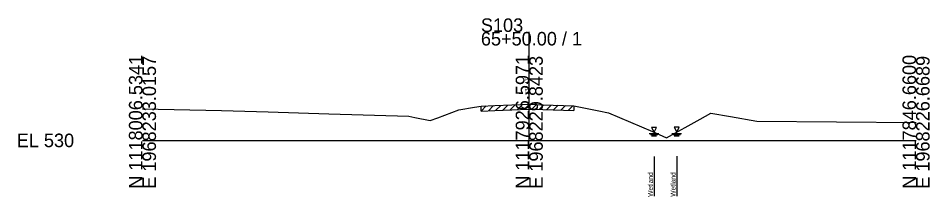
# Model space of a CAD drawing. Extents: x -26 to 163, y -10 to 45020.
# Drawn here: x -25.7 to 162.8, y 24488.3 to 24525.3 of the extents above; entities that cross this region are included whole.
import ezdxf

# ---------------------------------------------------------------- set-up
doc = ezdxf.new("R2010")
doc.units = 0
for name, color, linetype in [('RD_GPK_XS_Cell', 7, 'Continuous'), ('RD_XS_ExGround', 7, 'Continuous'), ('RD_XS_ExPaveRet', 7, 'Continuous'), ('RD_XS_EXWetland', 7, 'Continuous'), ('RD_XS_TX_Elev_EX', 7, 'Continuous')]:
    doc.layers.add(name, color=color, linetype=linetype)

msp = doc.modelspace()

# ---------------------------------------------------------------- linework, layer by layer
at = {"layer": 'RD_GPK_XS_Cell'}
for p, q in [((80, 24500), (80, 24522.43)), ((0, 24500), (80, 24500)), ((80, 24500), (160, 24500))]:
    msp.add_line(p, q, dxfattribs=at)
at = {"layer": 'RD_XS_ExGround'}
for p, q in [((72.86, 24507.2), (79.89, 24507.48)), ((79.89, 24507.48), (82.8, 24507.37)), ((82.8, 24507.37), (89.2, 24507.15)), ((0, 24506.55), (16.38, 24506.19)), ((16.38, 24506.19), (26.01, 24505.93)), ((26.01, 24505.93), (38.54, 24505.52)), ((38.54, 24505.52), (55.09, 24504.98)), ((61.07, 24504.69), (65.47, 24506.33)), ((65.47, 24506.33), (68.7, 24506.86)), ((68.7, 24506.86), (70.04, 24507.08)), ((70.04, 24507.08), (72.86, 24507.2)), ((89.2, 24507.15), (94.37, 24506.12)), ((94.37, 24506.12), (96.38, 24505.69)), ((96.38, 24505.69), (105.48, 24501.84)), ((115.34, 24504.4), (117.53, 24505.64)), ((117.53, 24505.64), (121.62, 24504.94)), ((55.09, 24504.98), (56.34, 24504.75)), ((56.34, 24504.75), (59.53, 24504.1)), ((59.53, 24504.1), (61.07, 24504.69)), ((108.41, 24500.55), (115.34, 24504.4)), ((121.62, 24504.94), (127.08, 24504.01)), ((127.08, 24504.01), (160, 24503.68)), ((105.48, 24501.84), (108.41, 24500.55))]:
    msp.add_line(p, q, dxfattribs=at)
at = {"layer": 'RD_XS_ExPaveRet'}
for p, q in [((76.04, 24506.32), (77.09, 24507.37)), ((77.54, 24506.38), (78.59, 24507.42)), ((79.04, 24506.44), (80.07, 24507.47)), ((80.54, 24506.45), (81.51, 24507.42)), ((82.04, 24506.4), (83.01, 24507.36)), ((70.04, 24506.08), (71.09, 24507.12)), ((70.04, 24506.08), (70.04, 24507.08)), ((70.04, 24506.08), (72.86, 24506.2)), ((71.54, 24506.14), (72.59, 24507.19)), ((72.86, 24506.2), (79.89, 24506.48)), ((73.04, 24506.21), (74.09, 24507.25)), ((74.54, 24506.27), (75.59, 24507.31)), ((79.89, 24506.48), (82.8, 24506.37)), ((82.8, 24506.37), (89.2, 24506.15)), ((83.54, 24506.34), (84.51, 24507.31)), ((85.04, 24506.29), (86.01, 24507.26)), ((86.54, 24506.24), (87.51, 24507.21)), ((88.04, 24506.19), (89.01, 24507.15)), ((89.2, 24507.15), (89.2, 24506.15))]:
    msp.add_line(p, q, dxfattribs=at)
at = {"layer": 'RD_XS_EXWetland'}
for p, q in [((105.32, 24502.69), (105.82, 24501.69)), ((106.32, 24502.69), (105.32, 24502.69)), ((105.82, 24501.69), (106.32, 24502.69)), ((110, 24502.71), (110.5, 24501.71)), ((111, 24502.71), (110, 24502.71)), ((110.5, 24501.71), (111, 24502.71)), ((104.82, 24501.44), (106.82, 24501.44)), ((105.07, 24501.19), (106.57, 24501.19)), ((105.32, 24500.94), (106.32, 24500.94)), ((109.5, 24501.46), (111.5, 24501.46)), ((109.75, 24501.21), (111.25, 24501.21)), ((110, 24500.96), (111, 24500.96)), ((105.82, 24496.69), (105.82, 24488.44)), ((110.5, 24496.71), (110.5, 24488.46))]:
    msp.add_line(p, q, dxfattribs=at)

# ---------------------------------------------------------------- texts
at = {"layer": 'RD_GPK_XS_Cell'}
for s, p in [('S103', (70, 24522.43)), ('65+50.00 / 1', (70, 24519.63)), ('EL 530', (-26, 24498.6))]:
    msp.add_text(s, height=2.8, dxfattribs=at).set_placement(p)
for s, p in [('N 1118006.5341', (0, 24490)), ('E 1968233.0157', (2.8, 24490)), ('N 1117926.5971', (80, 24490)), ('E 1968229.8423', (82.8, 24490)), ('N 1117846.6600', (160, 24490)), ('E 1968226.6689', (162.8, 24490))]:
    msp.add_text(s, height=2.8, rotation=90, dxfattribs=at).set_placement(p)
at = {"layer": 'RD_XS_EXWetland'}
for p in [(105.57, 24488.34), (110.25, 24488.35)]:
    msp.add_text('Wetland ', height=1, rotation=90, dxfattribs=at).set_placement(p)
at = {"layer": 'RD_XS_TX_Elev_EX'}
msp.add_text('537.47', height=0.8, rotation=90, dxfattribs=at).set_placement((79.9, 24509.47))

doc.saveas('drawing.dxf')
